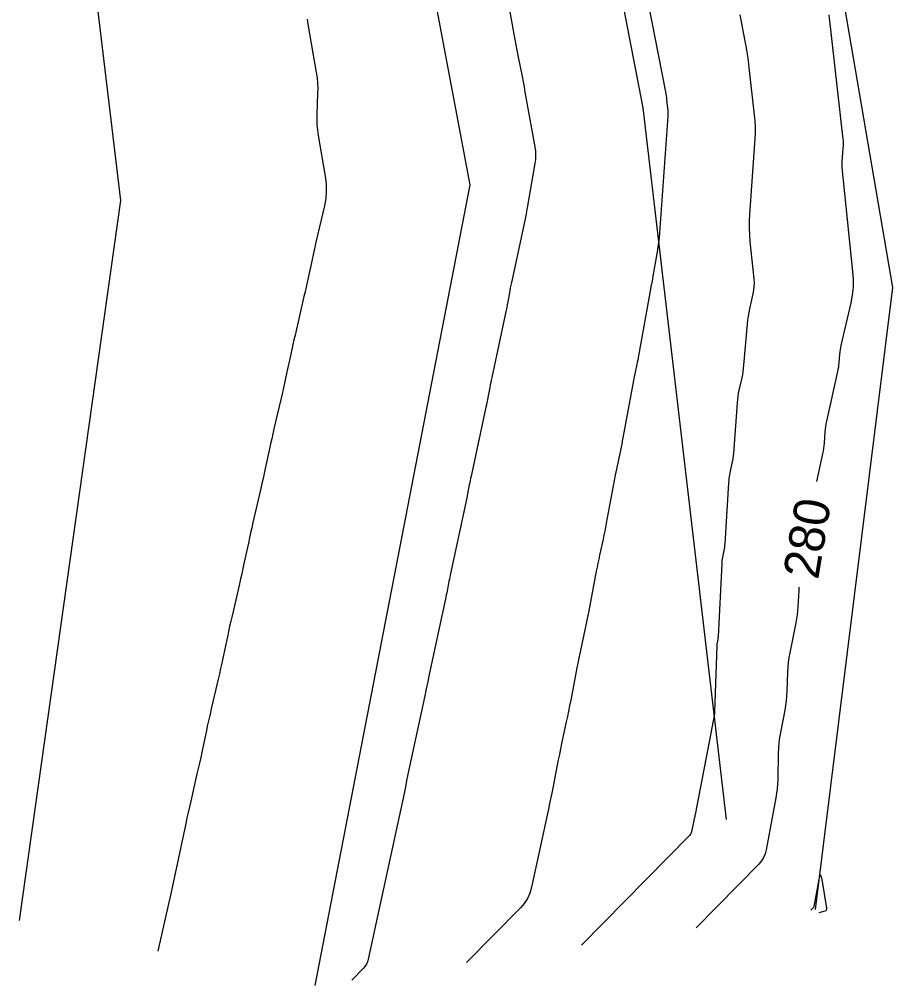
# Model space of a CAD drawing. Extents: x 1574966 to 1597594, y 720505 to 737840.
# Drawn here: x 1577987.9 to 1578134.8, y 723745.2 to 723907.8 of the extents above; entities that cross this region are included whole.
import ezdxf

# ---------------------------------------------------------------- set-up
doc = ezdxf.new("R2010")
doc.units = 0
for name, color, linetype in [('R_Contour Annot', 7, 'Continuous'), ('R_Contours', 7, 'Continuous'), ('S_BREAKLINE', 7, 'Continuous')]:
    doc.layers.add(name, color=color, linetype=linetype)

msp = doc.modelspace()

# ---------------------------------------------------------------- linework, layer by layer
at = {"layer": 'R_Contours'}
for points in [[(1578069.69, 723913.13), (1578071.1, 723905.26), (1578071.26, 723904.37), (1578071.43, 723903.48), (1578071.6, 723902.6), (1578071.77, 723901.71), (1578072.46, 723898.16), (1578072.63, 723897.27), (1578072.8, 723896.39), (1578072.96, 723895.5), (1578073.12, 723894.61), (1578074.61, 723886.31), (1578074.71, 723885.6), (1578074.74, 723884.9), (1578074.71, 723884.19), (1578074.62, 723883.49), (1578073.33, 723876.07), (1578073.24, 723875.54), (1578073.14, 723875.01), (1578073.03, 723874.48), (1578072.92, 723873.95), (1578070.78, 723863.98), (1578070.68, 723863.51), (1578070.58, 723863.04), (1578070.49, 723862.57), (1578070.41, 723862.1), (1578070.07, 723860.22), (1578069.98, 723859.75), (1578069.89, 723859.28), (1578069.8, 723858.81), (1578069.7, 723858.35), (1578067.36, 723847.49), (1578067.27, 723847.08), (1578067.19, 723846.66), (1578067.11, 723846.25), (1578067.03, 723845.83), (1578066.72, 723844.16), (1578066.64, 723843.74), (1578066.56, 723843.32), (1578066.48, 723842.91), (1578066.39, 723842.49), (1578063.89, 723830.91), (1578063.81, 723830.54), (1578063.74, 723830.17), (1578063.66, 723829.79), (1578063.59, 723829.42), (1578063.31, 723827.93), (1578063.24, 723827.56), (1578063.17, 723827.19), (1578063.09, 723826.82), (1578063.02, 723826.45), (1578060.38, 723814.25), (1578060.31, 723813.92), (1578060.24, 723813.58), (1578060.18, 723813.25), (1578060.11, 723812.92), (1578059.86, 723811.58), (1578059.8, 723811.25), (1578059.73, 723810.92), (1578059.66, 723810.58), (1578059.59, 723810.25), (1578056.84, 723797.53), (1578056.78, 723797.23), (1578056.72, 723796.93), (1578056.66, 723796.64), (1578056.6, 723796.34), (1578056.37, 723795.14), (1578056.31, 723794.84), (1578056.25, 723794.54), (1578056.19, 723794.24), (1578056.12, 723793.94), (1578053.28, 723780.77), (1578053.22, 723780.5), (1578053.16, 723780.23), (1578053.11, 723779.96), (1578053.06, 723779.69), (1578052.85, 723778.62), (1578052.79, 723778.35), (1578052.74, 723778.08), (1578052.68, 723777.81), (1578052.63, 723777.54), (1578046.59, 723749.62), (1578046.47, 723749.19), (1578046.29, 723748.79), (1578046.05, 723748.42), (1578045.76, 723748.08), (1578043.83, 723746.13)], [(1578093.7, 723910.43), (1578096.58, 723895.55), (1578096.64, 723895.22), (1578096.69, 723894.88), (1578096.74, 723894.55), (1578096.78, 723894.21), (1578096.93, 723892.85), (1578096.96, 723892.52), (1578096.98, 723892.18), (1578096.98, 723891.84), (1578096.96, 723891.5), (1578095.58, 723871.82), (1578095.52, 723871.03), (1578095.43, 723870.24), (1578095.33, 723869.45), (1578095.2, 723868.67), (1578094.43, 723864.21), (1578094.4, 723864.09), (1578094.38, 723863.96), (1578094.35, 723863.84), (1578094.33, 723863.71), (1578094.22, 723863.21), (1578094.19, 723863.08), (1578094.17, 723862.96), (1578094.14, 723862.83), (1578094.12, 723862.71), (1578092.05, 723851.14), (1578091.98, 723850.8), (1578091.92, 723850.45), (1578091.85, 723850.1), (1578091.78, 723849.76), (1578091.48, 723848.38), (1578091.41, 723848.04), (1578091.34, 723847.69), (1578091.27, 723847.35), (1578091.2, 723847), (1578089.43, 723837.35), (1578089.33, 723836.82), (1578089.23, 723836.3), (1578089.12, 723835.77), (1578089.01, 723835.25), (1578088.56, 723833.15), (1578088.45, 723832.63), (1578088.34, 723832.1), (1578088.24, 723831.58), (1578088.14, 723831.05), (1578086.63, 723823.02), (1578086.5, 723822.34), (1578086.37, 723821.66), (1578086.23, 723820.99), (1578086.09, 723820.32), (1578085.51, 723817.62), (1578085.36, 723816.95), (1578085.22, 723816.28), (1578085.09, 723815.6), (1578084.96, 723814.92), (1578083.69, 723808.27), (1578083.54, 723807.46), (1578083.38, 723806.66), (1578083.21, 723805.86), (1578083.04, 723805.06), (1578082.35, 723801.86), (1578082.18, 723801.06), (1578082.02, 723800.26), (1578081.85, 723799.46), (1578081.7, 723798.66), (1578080.65, 723793.19), (1578080.47, 723792.28), (1578080.29, 723791.37), (1578080.1, 723790.46), (1578079.9, 723789.55), (1578079.12, 723785.92), (1578078.92, 723785.01), (1578078.74, 723784.1), (1578078.55, 723783.19), (1578078.37, 723782.28), (1578077.51, 723777.86), (1578077.31, 723776.86), (1578077.11, 723775.85), (1578076.9, 723774.85), (1578076.69, 723773.85), (1578074.07, 723761.75), (1578073.79, 723760.77), (1578073.38, 723759.86), (1578072.84, 723759.02), (1578072.18, 723758.25), (1578063.13, 723749.06)], [(1578109.09, 723908.52), (1578109.95, 723904.1), (1578110.15, 723903), (1578110.33, 723901.89), (1578110.49, 723900.78), (1578110.62, 723899.66), (1578111.53, 723891.62), (1578111.61, 723890.65), (1578111.66, 723889.67), (1578111.65, 723888.69), (1578111.61, 723887.71), (1578110.71, 723874.96), (1578110.66, 723873.81), (1578110.65, 723872.67), (1578110.7, 723871.52), (1578110.79, 723870.38), (1578111.44, 723864.1), (1578111.48, 723863.46), (1578111.46, 723862.83), (1578111.4, 723862.2), (1578111.28, 723861.57), (1578110.71, 723859.07), (1578110.58, 723858.45), (1578110.47, 723857.82), (1578110.38, 723857.18), (1578110.31, 723856.55), (1578109.73, 723849.56), (1578109.68, 723849.03), (1578109.61, 723848.5), (1578109.52, 723847.98), (1578109.41, 723847.45), (1578108.94, 723845.37), (1578108.84, 723844.85), (1578108.75, 723844.32), (1578108.68, 723843.79), (1578108.63, 723843.26), (1578108.01, 723834.73), (1578107.97, 723834.31), (1578107.92, 723833.9), (1578107.85, 723833.49), (1578107.77, 723833.08), (1578107.42, 723831.46), (1578107.34, 723831.05), (1578107.27, 723830.64), (1578107.23, 723830.23), (1578107.19, 723829.81), (1578106.57, 723819.54), (1578106.54, 723819.26), (1578106.51, 723818.98), (1578106.47, 723818.7), (1578106.41, 723818.42), (1578106.18, 723817.3), (1578106.13, 723817.02), (1578106.09, 723816.74), (1578106.05, 723816.46), (1578106.04, 723816.18), (1578105.45, 723803.95), (1578105.44, 723803.81), (1578105.42, 723803.68), (1578105.4, 723803.54), (1578105.38, 723803.41), (1578105.27, 723802.87), (1578105.24, 723802.74), (1578105.23, 723802.6), (1578105.21, 723802.47), (1578105.21, 723802.33), (1578104.82, 723791.22), (1578104.81, 723790.92), (1578104.78, 723790.61), (1578104.74, 723790.31), (1578104.69, 723790.01), (1578104.35, 723788.26), (1578104.34, 723788.23), (1578104.34, 723788.2), (1578104.33, 723788.17), (1578104.33, 723788.15), (1578104.3, 723788.04), (1578104.3, 723788.01), (1578104.29, 723787.98), (1578104.29, 723787.95), (1578104.28, 723787.92), (1578101.57, 723773.98), (1578101.53, 723773.8), (1578101.5, 723773.62), (1578101.46, 723773.44), (1578101.42, 723773.26), (1578100.95, 723771.08), (1578100.9, 723770.91), (1578100.83, 723770.74), (1578100.73, 723770.59), (1578100.61, 723770.45), (1578082.44, 723751.99)], [(1578124.08, 723908.55), (1578126.43, 723887.6), (1578126.45, 723887.38), (1578126.46, 723887.16), (1578126.46, 723886.95), (1578126.45, 723886.73), (1578126.25, 723883.87), (1578126.24, 723883.61), (1578126.24, 723883.36), (1578126.25, 723883.1), (1578126.27, 723882.85), (1578128.07, 723865.36), (1578128.15, 723864.03), (1578128.13, 723862.7), (1578127.99, 723861.37), (1578127.74, 723860.06), (1578126.1, 723852.91), (1578126.03, 723852.54), (1578125.96, 723852.18), (1578125.91, 723851.81), (1578125.87, 723851.44), (1578125.75, 723849.96), (1578125.71, 723849.59), (1578125.66, 723849.22), (1578125.6, 723848.85), (1578125.53, 723848.49), (1578123.66, 723840.16), (1578123.57, 723839.7), (1578123.5, 723839.25), (1578123.44, 723838.79), (1578123.39, 723838.33), (1578123.26, 723836.48), (1578123.22, 723836.02), (1578123.16, 723835.56), (1578123.09, 723835.1), (1578123, 723834.65), (1578121.98, 723829.99)], [(1578036.31, 723907.8), (1578036.43, 723906.98), (1578037.87, 723898.8), (1578037.99, 723897.93), (1578038.07, 723897.05), (1578038.11, 723896.17), (1578038.09, 723895.29), (1578037.94, 723891.76), (1578037.93, 723890.88), (1578037.96, 723890), (1578038.04, 723889.12), (1578038.17, 723888.25), (1578039.37, 723881.36), (1578039.52, 723880.11), (1578039.55, 723878.86), (1578039.45, 723877.62), (1578039.23, 723876.38), (1578037.86, 723870.51), (1578037.69, 723869.73), (1578037.51, 723868.95), (1578037.34, 723868.17), (1578037.17, 723867.38), (1578036.49, 723864.25), (1578036.32, 723863.47), (1578036.15, 723862.69), (1578035.97, 723861.91), (1578035.79, 723861.13), (1578034.29, 723854.65), (1578034.11, 723853.85), (1578033.92, 723853.04), (1578033.75, 723852.23), (1578033.57, 723851.42), (1578032.88, 723848.19), (1578032.7, 723847.38), (1578032.52, 723846.57), (1578032.34, 723845.76), (1578032.16, 723844.96), (1578030.74, 723838.85), (1578030.55, 723838.02), (1578030.36, 723837.18), (1578030.17, 723836.35), (1578029.99, 723835.51), (1578029.28, 723832.17), (1578029.1, 723831.34), (1578028.91, 723830.51), (1578028.73, 723829.67), (1578028.54, 723828.84), (1578027.21, 723823.1), (1578027.01, 723822.24), (1578026.81, 723821.38), (1578026.63, 723820.52), (1578026.44, 723819.66), (1578025.7, 723816.22), (1578025.52, 723815.35), (1578025.33, 723814.49), (1578025.13, 723813.64), (1578024.94, 723812.78), (1578023.69, 723807.41), (1578023.49, 723806.53), (1578023.29, 723805.64), (1578023.1, 723804.75), (1578022.91, 723803.86), (1578022.15, 723800.31), (1578021.96, 723799.42), (1578021.76, 723798.54), (1578021.56, 723797.65), (1578021.36, 723796.77), (1578020.2, 723791.78), (1578020, 723790.87), (1578019.79, 723789.95), (1578019.59, 723789.04), (1578019.39, 723788.13), (1578018.61, 723784.46), (1578018.42, 723783.55), (1578018.22, 723782.63), (1578018.01, 723781.72), (1578017.8, 723780.81), (1578016.74, 723776.21), (1578016.52, 723775.27), (1578016.31, 723774.33), (1578016.11, 723773.39), (1578015.9, 723772.44), (1578013.45, 723760.89), (1578013.24, 723759.91), (1578013.02, 723758.93), (1578012.8, 723757.95), (1578012.58, 723756.97), (1578011.2, 723751)], [(1578119.03, 723812.24), (1578118.99, 723811.63), (1578118.86, 723808.91), (1578118.81, 723808.23), (1578118.74, 723807.55), (1578118.64, 723806.88), (1578118.52, 723806.21), (1578117.5, 723801.2), (1578117.36, 723800.4), (1578117.25, 723799.6), (1578117.17, 723798.79), (1578117.13, 723797.98), (1578117.01, 723794.74), (1578116.97, 723793.93), (1578116.89, 723793.12), (1578116.79, 723792.32), (1578116.65, 723791.52), (1578115.92, 723787.8), (1578115.77, 723786.91), (1578115.66, 723786.02), (1578115.58, 723785.12), (1578115.55, 723784.22), (1578115.46, 723779.87), (1578115.43, 723779.1), (1578115.37, 723778.32), (1578115.27, 723777.55), (1578115.15, 723776.79), (1578113.53, 723768.03), (1578113.35, 723767.36), (1578113.09, 723766.74), (1578112.73, 723766.16), (1578112.28, 723765.63), (1578101.74, 723754.93)], [(1578122.43, 723757.49), (1578123.45, 723757.77), (1578123.59, 723757.83), (1578123.69, 723757.92), (1578123.73, 723758.05), (1578123.73, 723758.2), (1578122.92, 723763.02), (1578122.79, 723763.61), (1578122.65, 723763.81), (1578122.51, 723763.61), (1578122.37, 723763.03), (1578121.53, 723758.49), (1578121.51, 723758.41), (1578121.47, 723758.34), (1578121.43, 723758.27), (1578121.38, 723758.21), (1578121.04, 723757.86)]]:
    msp.add_lwpolyline(points, dxfattribs=at)
at = {"layer": 'S_BREAKLINE'}
for p, q in [((1578134.8, 723862.63), (1578102.27, 724053.14)), ((1578092.82, 723892.89), (1578064.72, 724039.7)), ((1578035.49, 724029.31), (1578063.69, 723879.92)), ((1577988.37, 724015.7), (1578004.94, 723877.29)), ((1578106.85, 723773.13), (1578092.82, 723892.89)), ((1578063.69, 723879.92), (1578037.6, 723745.18)), ((1578004.94, 723877.29), (1577987.92, 723756.14)), ((1578121.84, 723757.98), (1578134.8, 723862.63))]:
    msp.add_line(p, q, dxfattribs=at)

# ---------------------------------------------------------------- texts
at = {"layer": 'R_Contour Annot'}
msp.add_text('280', height=6, rotation=80.555, dxfattribs=at).set_placement((1578122.26, 723813.37))

doc.saveas('drawing.dxf')
